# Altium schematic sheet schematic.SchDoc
size 431 x 279 mm; Date: Not shown in title block; ApprovedBy: Not shown in title block; CheckedBy: Not shown in title block; Author: Not shown in title block; CompanyName: Not shown in title block; Engineer: Not shown in title block; Organization: Not shown in title block; Address1: Not shown in title block; Address2: Not shown in title block; Address3: Not shown in title block; Address4: Not shown in title block; DocumentNumber: 1; Revision: Use project parameter SCH_Rev; SheetNumber: 1; SheetTotal: 1; PageSetup: Record=PageOptions|CenterHorizontal=True|CenterVertical=True|PrintScale=1.00|XCorrection=1.00|YCorrection=1.00|PrintKind=0|BorderSize=5000000|LeftOffset=0|BottomOffset=0|Orientation=2|PaperLength=1000|PaperWidth=1000|Scale=100|PaperSource=15|PrintQuality=600|MediaType=1|DitherType=10|PaperKind=Letter|PrintScaleMode=1
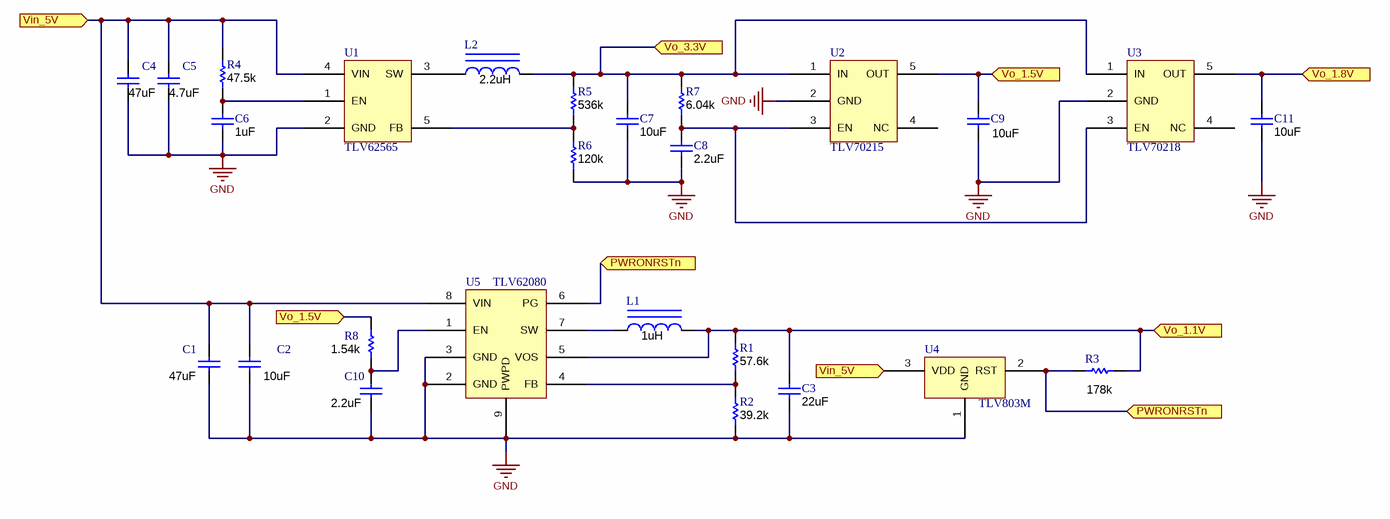
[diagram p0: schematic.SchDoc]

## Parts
C1  ValueDisplayed: 47uF  [2220]  (hidden comment: VJ2220Y224KBEAT4X)
C2  ValueDisplayed: 10uF  [2220]  (hidden comment: VJ2220Y224KBEAT4X)
C3  ValueDisplayed: 22uF  [2220]  (hidden comment: VJ2220Y224KBEAT4X)
C4  ValueDisplayed: 47uF  [2220]  (hidden comment: VJ2220Y224KBEAT4X)
C5  ValueDisplayed: 4.7uF  [2220]  (hidden comment: VJ2220Y224KBEAT4X)
C6  ValueDisplayed: 1uF  [2220]  (hidden comment: VJ2220Y224KBEAT4X)
C7  ValueDisplayed: 10uF  [2220]  (hidden comment: VJ2220Y224KBEAT4X)
C8  ValueDisplayed: 2.2uF  [2220]  (hidden comment: VJ2220Y224KBEAT4X)
C9  ValueDisplayed: 10uF  [2220]  (hidden comment: VJ2220Y224KBEAT4X)
C10  ValueDisplayed: 2.2uF  [2220]  (hidden comment: VJ2220Y224KBEAT4X)
C11  ValueDisplayed: 10uF  [2220]  (hidden comment: VJ2220Y224KBEAT4X)
L1  ValueDisplayed: 1uH  [XPL2010]
L2  ValueDisplayed: 2.2uH  [XPL2010]
R1  value 57.6k  [0603]  (hidden comment: RT0603DRE07976RL)
R2  value 39.2k  [0603]  (hidden comment: RT0603DRE07976RL)
R3  value 178k  [0603]  (hidden comment: RT0603DRE07976RL)
R4  value 47.5k  [0603]  (hidden comment: RT0603DRE07976RL)
R5  value 536k  [0603]  (hidden comment: RT0603DRE07976RL)
R6  value 120k  [0603]  (hidden comment: RT0603DRE07976RL)
R7  value 6.04k  [0603]  (hidden comment: RT0603DRE07976RL)
R8  value 1.54k  [0603]  (hidden comment: RT0603DRE07976RL)
U1  TLV62565
U2  TLV70215
U3  TLV70218
U4  TLV803M
U5  TLV62080

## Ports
PWRONRSTn, Vin_5V, Vo_1.1V, Vo_1.5V, Vo_1.8V, Vo_3.3V

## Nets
GND: C1.2 C2.2 C3.2 C4.2 C5.2 C6.2 C7.2 C8.2 C9.2 C10.2 C11.2 R2.1 R6.1 U1.2(GND) U2.2(GND) U3.2(GND) U4.1(GND) U5.2(GND) U5.3(GND) U5.9(PWPD)
PWRONRSTn: R3.2 U4.2(RST) U5.6(PG) ; port PWRONRSTn
Vin_5V: C1.1 C2.1 C4.1 C5.1 R4.2 U1.4(VIN) U4.3(VDD) U5.8(VIN) ; port Vin_5V
Vo_1.1V: C3.1 L1.2 R1.2 R3.1 U5.5(VOS) ; port Vo_1.1V
Vo_1.5V: C9.1 R8.2 U2.5(OUT) ; port Vo_1.5V
Vo_1.8V: C11.1 U3.5(OUT) ; port Vo_1.8V
Vo_3.3V: C7.1 L2.2 R5.2 R7.2 U2.1(IN) U3.1(IN) ; port Vo_3.3V
NetC6_1: C6.1 R4.1 U1.1(EN)
NetC8_1: C8.1 R7.1 U2.3(EN) U3.3(EN)
NetC10_1: C10.1 R8.1 U5.1(EN)
NetL1_1: L1.1 U5.7(SW)
NetL2_1: L2.1 U1.3(SW)
NetR1_1: R1.1 R2.2 U5.4(FB)
NetR5_1: R5.1 R6.2 U1.5(FB)

Not connected (* = marked no-connect by the designer): U2 4(NC); U3 4(NC)

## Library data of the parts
C1-C11 = VJ2220Y224KBEAT4X: CAP, CERM, 0.22uF, 500V, +/-10%, X7R, 2220; Manufacturer: Vishay-Vitramon; Polarized: N; CompType: Capacitor; U/M: EA; Cap_F: 0.00000022; Tolerance_%: 10; Value1: Unknown; VDC_V: 500; TaMin_C: -55; TaMax_C: 125
L1 L2 = XPL2010-822MLB: Inductor, Shielded, Composite, 8.2uH, 0.67A, 0.46 ohm, SMD; Manufacturer: Coilcraft; Ind_H: 8.2E-6; Imax_A: 0.67; Irms: 0.75A @ 40C rise; Isat: 0.67A @ 30% inductance drop; DCR_ohm: 0.46; U/M: EA
R1-R8 = RT0603DRE07976RL: RES, 976 ohm, 0.5%, 0.1W, 0603; Manufacturer: Yageo America; CompType: Resistor; Res_ohm: 976; Value_Code: 976R; Tolerance_%: 0.5; Power_W: 0.1; VDC_V: 75; TempCo: 50 ppm/C; EIA_Code: E192; U/M: EA
U3 = TLV70215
